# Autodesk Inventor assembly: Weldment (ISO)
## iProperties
Length Units: 11269
Angle Units: 11283
Time Units: 11279
Mass Units: 11290
Length Display Precision: 3
Angle Display Precision: 2
Part Number: Weldment (ISO)
Document SubType Name: Weldment
Created: 2002-06
Designer: smithga
Part Number: Ens_tuyauterie_sortie
Created: 2008-04
Designer: plup
Material: Aluminum soudé-6061
Control State: 0
Master: False
Shininess: 64.0
Angle Units: 11279
Time Units: 11290
Mass Units: 11283
Compacted: True
Density: 0.0
Volumn: 0.0
Area: 0.0
PropertySet Name: Model Information
Author: plup
